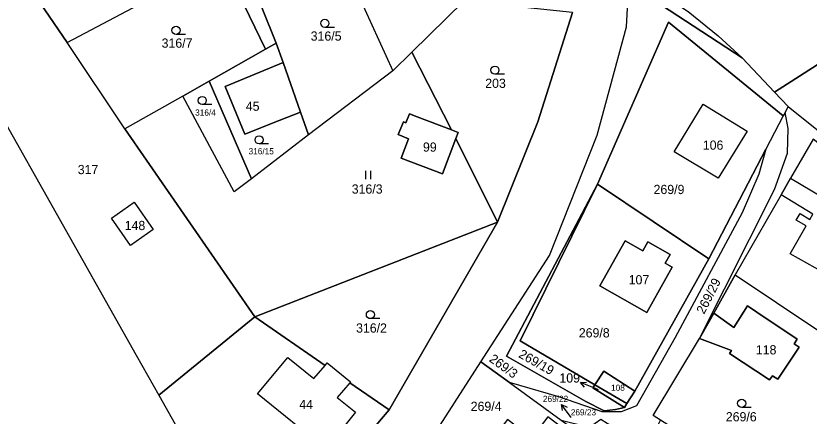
# Model space of a CAD drawing. Extents: x -590606 to -587796, y -1065936 to -1062515.
# Drawn here: x -589191 to -589044.8, y -1064528.5 to -1064454.8 of the extents above; entities that cross this region are included whole.
import ezdxf

# ---------------------------------------------------------------- set-up
doc = ezdxf.new("R2010")
doc.units = 0
for name, color, linetype in [('Parcela nároku', 7, 'Continuous'), ('Parcelní číslo', 7, 'Continuous'), ('Vrstva 30', 7, 'Continuous')]:
    doc.layers.add(name, color=color, linetype=linetype)

msp = doc.modelspace()

# ---------------------------------------------------------------- linework, layer by layer
at = {"layer": 'Parcela nároku'}
for points in [[(-589115.31, -1064437.58), (-589122.6, -1064422.32), (-589132.89, -1064400.67), (-589145.56, -1064374.76), (-589153.23, -1064385.7), (-589150.61, -1064384.42), (-589149.77, -1064386.15), (-589148.31, -1064385.41), (-589145.3, -1064391.43), (-589143.1, -1064390.21), (-589141.76, -1064392.64), (-589144.07, -1064393.88), (-589140.03, -1064401.95), (-589146.68, -1064405.04), (-589154.26, -1064391.41), (-589136.97, -1064430.89), (-589121.53, -1064464.86), (-589118, -1064461.45), (-589108.39, -1064452.07)], [(-589151.26, -1064439.02), (-589150.69, -1064440.44), (-589145.63, -1064453.19), (-589143.01, -1064459.79), (-589144.95, -1064460.89), (-589152.91, -1064444.49), (-589160.29, -1064423.26), (-589159.06, -1064422.32)], [(-589166.49, -1064427.99), (-589190.58, -1064446.38), (-589181.56, -1064459.68), (-589152.91, -1064444.49), (-589160.29, -1064423.26)], [(-589054.48, -1064435.41), (-589077.97, -1064446.72), (-589067.07, -1064453.97), (-589061.52, -1064458.43), (-589057.13, -1064462.5), (-589051.17, -1064468.81), (-589021.42, -1064449.73), (-589042.45, -1064423.68), (-589046.93, -1064428.46)], [(-589151.26, -1064439.02), (-589136.97, -1064430.89), (-589121.53, -1064464.86), (-589137.07, -1064476.7), (-589138.51, -1064472.49), (-589141.75, -1064463.34), (-589143.01, -1064459.79), (-589145.63, -1064453.19), (-589143.02, -1064451.87), (-589135.34, -1064447.9), (-589141.74, -1064435.9), (-589149.27, -1064439.72), (-589150.69, -1064440.44)], [(-589170.89, -1064475.6), (-589181.56, -1064459.68), (-589190.58, -1064446.38), (-589198.19, -1064435.18), (-589208.79, -1064446.47), (-589168.83, -1064517.27), (-589164.65, -1064524.67), (-589146.94, -1064510.23)], [(-589181.56, -1064459.68), (-589152.91, -1064444.49), (-589144.95, -1064460.89), (-589155.37, -1064466.8), (-589160.23, -1064469.56), (-589170.89, -1064475.6)], [(-589232.4, -1064471.45), (-589208.79, -1064446.47), (-589168.83, -1064517.27), (-589164.65, -1064524.67), (-589161.07, -1064530.98), (-589156.51, -1064536.45), (-589159.83, -1064537.55), (-589201.82, -1064551.44)], [(-589078.02, -1064448.81), (-589077.97, -1064446.72), (-589067.07, -1064453.97), (-589061.52, -1064458.43), (-589057.13, -1064462.5)], [(-589057.13, -1064462.5), (-589051.17, -1064468.81), (-589048.65, -1064471.48), (-589049.2, -1064472.55), (-589049.53, -1064473.18), (-589070.66, -1064455.95), (-589083.76, -1064485.8), (-589100.58, -1064517.5), (-589085.95, -1064525.82), (-589082.57, -1064527.52), (-589080.47, -1064527.32), (-589078.82, -1064526.93), (-589078.35, -1064526.19), (-589076.87, -1064523.9), (-589063.23, -1064499.51), (-589052.72, -1064479.3), (-589054.06, -1064483.94), (-589057.13, -1064491.06), (-589069.47, -1064514.03), (-589076.57, -1064526.63), (-589079.42, -1064527.74), (-589082.89, -1064527.75), (-589090.91, -1064524.94), (-589100.01, -1064522.33), (-589105.28, -1064518.51), (-589092.65, -1064498.9), (-589083.82, -1064476.76), (-589078.44, -1064456.79), (-589078.02, -1064448.81)], [(-589021.42, -1064449.73), (-589051.17, -1064468.81), (-589048.65, -1064471.48), (-589029.39, -1064486.89), (-589024.72, -1064490.53), (-589014.96, -1064485.26), (-588999.69, -1064476.66)], [(-589109.44, -1064476.24), (-589109.87, -1064477.37), (-589102.2, -1064492.78), (-589094.76, -1064474.31), (-589088.39, -1064454.14), (-589108.39, -1064452.07), (-589118, -1064461.45), (-589110.67, -1064475.77)], [(-589083.76, -1064485.8), (-589070.66, -1064455.95), (-589049.53, -1064473.18), (-589052.72, -1064479.3), (-589063.23, -1064499.51)], [(-589155.37, -1064466.8), (-589144.95, -1064460.89), (-589143.01, -1064459.79), (-589141.75, -1064463.34), (-589146.05, -1064465.13), (-589152.42, -1064467.78), (-589148.79, -1064476.54), (-589142.48, -1064474.06), (-589138.51, -1064472.49), (-589137.07, -1064476.7), (-589147.59, -1064484.81)], [(-589147.59, -1064484.81), (-589150.73, -1064487.19), (-589160.23, -1064469.56), (-589170.89, -1064475.6), (-589146.94, -1064510.23), (-589102.2, -1064492.78), (-589109.87, -1064477.37), (-589112.36, -1064483.84), (-589119.99, -1064480.97), (-589118.61, -1064477.4), (-589120.53, -1064476.65), (-589119.56, -1064474.27), (-589119.09, -1064474.45), (-589118.45, -1064472.8), (-589117.04, -1064473.35), (-589110.67, -1064475.77), (-589118, -1064461.45), (-589121.53, -1064464.86), (-589137.07, -1064476.7)], [(-589152.42, -1064467.78), (-589146.05, -1064465.13), (-589141.75, -1064463.34), (-589138.51, -1064472.49), (-589142.48, -1064474.06), (-589148.79, -1064476.54)], [(-589155.37, -1064466.8), (-589147.59, -1064484.81), (-589150.73, -1064487.19), (-589160.23, -1064469.56)], [(-589064.29, -1064471.06), (-589056.21, -1064475.99), (-589061.5, -1064484.68), (-589069.67, -1064479.81)], [(-589056.21, -1064475.99), (-589061.5, -1064484.68), (-589069.67, -1064479.81), (-589064.29, -1064471.06)], [(-589118.61, -1064477.4), (-589119.99, -1064480.97), (-589112.36, -1064483.84), (-589109.87, -1064477.37), (-589109.44, -1064476.24), (-589110.67, -1064475.77), (-589117.04, -1064473.35), (-589118.45, -1064472.8), (-589119.09, -1064474.45), (-589119.56, -1064474.27), (-589120.53, -1064476.65)], [(-589076.57, -1064526.63), (-589079.42, -1064527.74), (-589082.89, -1064527.75), (-589090.91, -1064524.94), (-589100.01, -1064522.33), (-589090.45, -1064529.26), (-589085.24, -1064530.57), (-589083.14, -1064529.09), (-589080.83, -1064530.54), (-589063.47, -1064541.46), (-589072.75, -1064530.48), (-589072.17, -1064529.26), (-589073.49, -1064528.42), (-589065, -1064514.23), (-589051.15, -1064486.78), (-589048.73, -1064480.06), (-589048.6, -1064475.49), (-589049.2, -1064472.55), (-589049.53, -1064473.18), (-589052.72, -1064479.3), (-589054.06, -1064483.94), (-589057.13, -1064491.06), (-589069.47, -1064514.03)], [(-589040.6, -1064502.91), (-589048.23, -1064498.62), (-589045.3, -1064493.48), (-589047.13, -1064492.43), (-589046.44, -1064491.21), (-589044.61, -1064492.26), (-589044.06, -1064491.3), (-589049.94, -1064487.74), (-589058.39, -1064502.47), (-589035.51, -1064517.76), (-589021.25, -1064495.37), (-589044.04, -1064477.46), (-589048.18, -1064484.68), (-589042.27, -1064488.16), (-589042.15, -1064487.94), (-589034.46, -1064492.34)], [(-589046.44, -1064491.21), (-589044.61, -1064492.26), (-589044.06, -1064491.3), (-589049.94, -1064487.74), (-589048.18, -1064484.68), (-589042.27, -1064488.16), (-589042.15, -1064487.94), (-589034.46, -1064492.34), (-589040.6, -1064502.91), (-589048.23, -1064498.62), (-589045.3, -1064493.48), (-589047.13, -1064492.43)], [(-589100.58, -1064517.5), (-589083.76, -1064485.8), (-589098.01, -1064514.65), (-589084.24, -1064522.73), (-589084.62, -1064523.3), (-589078.82, -1064526.93), (-589080.47, -1064527.32), (-589082.57, -1064527.52), (-589085.95, -1064525.82)], [(-589083.76, -1064485.8), (-589063.23, -1064499.51), (-589076.87, -1064523.9), (-589082.61, -1064520.26), (-589084.24, -1064522.73), (-589098.01, -1064514.65)], [(-589169.84, -1064497.07), (-589173.37, -1064492.04), (-589169.2, -1064489.1), (-589165.66, -1064494.13)], [(-589173.37, -1064492.04), (-589169.2, -1064489.1), (-589165.66, -1064494.13), (-589169.84, -1064497.07)], [(-589129.31, -1064522.2), (-589129.44, -1064522.36), (-589122.18, -1064527.39), (-589102.2, -1064492.78), (-589146.94, -1064510.23), (-589134, -1064519.2), (-589133.61, -1064518.69)], [(-589074.47, -1064496.4), (-589075.41, -1064498.05), (-589078.65, -1064496.2), (-589083.36, -1064504.53), (-589074.68, -1064509.44), (-589070.01, -1064501.07), (-589071.3, -1064500.34), (-589070.38, -1064498.73)], [(-589074.68, -1064509.44), (-589083.36, -1064504.53), (-589078.65, -1064496.2), (-589075.41, -1064498.05), (-589074.47, -1064496.4), (-589070.38, -1064498.73), (-589071.3, -1064500.34), (-589070.01, -1064501.07)], [(-589073.49, -1064528.42), (-589065, -1064514.23), (-589059.07, -1064516.43), (-589059.42, -1064516.96), (-589052.04, -1064521.86), (-589051.51, -1064521.07), (-589050.55, -1064521.72), (-589046.57, -1064515.81), (-589047.52, -1064515.17), (-589046.98, -1064514.36), (-589054.41, -1064509.35), (-589056.13, -1064508.19), (-589058.63, -1064512.18), (-589062.32, -1064509.54), (-589058.39, -1064502.47), (-589035.51, -1064517.76), (-589051.04, -1064542.74), (-589072.17, -1064529.26)], [(-589065, -1064514.23), (-589062.97, -1064510.67), (-589062.32, -1064509.54), (-589058.63, -1064512.18), (-589056.13, -1064508.19), (-589054.41, -1064509.35), (-589046.98, -1064514.36), (-589047.52, -1064515.17), (-589046.57, -1064515.81), (-589050.55, -1064521.72), (-589051.51, -1064521.07), (-589052.04, -1064521.86), (-589059.42, -1064516.96), (-589059.07, -1064516.43)], [(-589129.44, -1064522.36), (-589131.76, -1064525.09), (-589128.4, -1064527.82), (-589133.87, -1064534.63), (-589146.45, -1064524.44), (-589140.87, -1064517.69), (-589136.06, -1064521.6), (-589134, -1064519.2), (-589146.94, -1064510.23), (-589164.65, -1064524.67), (-589161.07, -1064530.98), (-589156.51, -1064536.45), (-589143.75, -1064552.4), (-589134.1, -1064541.79), (-589130.39, -1064537.32), (-589123.98, -1064529.48), (-589122.18, -1064527.39)], [(-589131.76, -1064525.09), (-589128.4, -1064527.82), (-589133.87, -1064534.63), (-589146.45, -1064524.44), (-589140.87, -1064517.69), (-589136.06, -1064521.6), (-589134, -1064519.2), (-589133.61, -1064518.69), (-589129.31, -1064522.2), (-589129.44, -1064522.36)], [(-589105.28, -1064518.51), (-589100.01, -1064522.33), (-589090.45, -1064529.26), (-589086.97, -1064531.78), (-589093.87, -1064538.29), (-589088.84, -1064531.79), (-589092.91, -1064528.64), (-589095.97, -1064532.57), (-589100.35, -1064529.15), (-589108.67, -1064540.01), (-589115.01, -1064533.6)], [(-589084.24, -1064522.73), (-589082.61, -1064520.26), (-589076.87, -1064523.9), (-589078.35, -1064526.19)], [(-589084.62, -1064523.3), (-589084.24, -1064522.73), (-589078.35, -1064526.19), (-589078.82, -1064526.93)]]:
    msp.add_lwpolyline(points, close=True, dxfattribs=at)
for points in [[(-589219.53, -1064748.72), (-589186.36, -1064642.57), (-589183.62, -1064634.01), (-589183.45, -1064633.66), (-589181.35, -1064629.23), (-589179.39, -1064625.08), (-589169.88, -1064604.99), (-589163.72, -1064594.94), (-589149.8, -1064577.36), (-589123.77, -1064546.13), (-589122.47, -1064544.56), (-589115.01, -1064533.6), (-589105.28, -1064518.51), (-589092.65, -1064498.9), (-589083.82, -1064476.76), (-589078.44, -1064456.79), (-589078.02, -1064448.81)], [(-589088.39, -1064454.14), (-589094.76, -1064474.31), (-589102.2, -1064492.78), (-589122.18, -1064527.39), (-589123.98, -1064529.48), (-589130.39, -1064537.32), (-589134.1, -1064541.79), (-589143.75, -1064552.4), (-589146.65, -1064555.73), (-589149.4, -1064559.72), (-589167.86, -1064579.14), (-589174.88, -1064589.8), (-589180.97, -1064599.01), (-589185.08, -1064607.88), (-589192.01, -1064622.83)], [(-589044.04, -1064477.46), (-589048.18, -1064484.68), (-589049.94, -1064487.74), (-589058.39, -1064502.47), (-589062.32, -1064509.54), (-589062.97, -1064510.67), (-589065, -1064514.23), (-589051.15, -1064486.78), (-589048.73, -1064480.06), (-589048.6, -1064475.49), (-589049.2, -1064472.55), (-589048.65, -1064471.48), (-589029.39, -1064486.89)]]:
    msp.add_lwpolyline(points, dxfattribs=at)
at = {"layer": 'Parcelní číslo'}
for p, q in [((-589084.13, -1064523.44), (-589086.92, -1064522.34)), ((-589083.56, -1064523.67), (-589084.13, -1064523.44)), ((-589088.61, -1064528.8), (-589090.39, -1064526.38))]:
    msp.add_line(p, q, dxfattribs=at)
for points in [[(-589086.17, -1064523.17), (-589086.92, -1064522.34), (-589085.81, -1064522.24)], [(-589090.2, -1064527.48), (-589090.39, -1064526.38), (-589089.39, -1064526.89)]]:
    msp.add_lwpolyline(points, dxfattribs=at)
at = {"layer": 'Vrstva 30'}
for p, q in [((-589132.28, -1064456.88), (-589134.03, -1064456.88)), ((-589159.72, -1064458.18), (-589161.47, -1064458.18)), ((-589100.94, -1064465.52), (-589102.69, -1064465.52)), ((-589154.89, -1064471.1), (-589156.64, -1064471.1)), ((-589144.41, -1064478.36), (-589146.16, -1064478.36)), ((-589126.56, -1064483.34), (-589126.56, -1064484.84)), ((-589125.54, -1064484.84), (-589125.54, -1064483.34)), ((-589123.89, -1064510.56), (-589125.64, -1064510.56)), ((-589055.44, -1064526.92), (-589057.19, -1064526.92))]:
    msp.add_line(p, q, dxfattribs=at)
for centre in [(-589134.03, -1064456.13), (-589161.47, -1064457.43), (-589102.69, -1064464.77), (-589156.64, -1064470.35), (-589146.16, -1064477.61), (-589125.64, -1064509.81), (-589057.19, -1064526.17)]:
    msp.add_circle(centre, 0.75, dxfattribs=at)

# ---------------------------------------------------------------- texts
at = {"layer": 'Parcela nároku'}
for s, height, p in [('316/5', 1.7, (-589136.65, -1064459.33)), ('316/7', 1.7, (-589164.13, -1064460.63)), ('203', 1.7, (-589104.47, -1064468.03)), ('45', 1.7, (-589148.61, -1064472.25)), ('316/4', 1.14, (-589157.95, -1064473.15)), ('99', 1.7, (-589115.95, -1064479.79)), ('106', 1.7, (-589064.36, -1064479.43)), ('316/15', 1.14, (-589148.1, -1064480.28)), ('317', 1.7, (-589179.59, -1064483.93)), ('316/3', 1.7, (-589129.08, -1064487.52)), ('269/9', 1.7, (-589073.44, -1064487.6)), ('148', 1.7, (-589170.94, -1064494.24)), ('107', 1.7, (-589078.03, -1064504.24)), ('316/2', 1.7, (-589128.28, -1064513.13)), ('269/8', 1.7, (-589087.22, -1064514.02)), ('118', 1.7, (-589054.58, -1064517.15)), ('108', 1.14, (-589081.28, -1064523.86)), ('109', 0.1, (-589083.64, -1064523.67)), ('44', 1.7, (-589138.76, -1064527.22)), ('269/4', 1.7, (-589107.15, -1064527.56)), ('269/6', 1.7, (-589060.12, -1064529.49))]:
    msp.add_text(s, height=height, dxfattribs=at).set_placement(p)
for s, rotation, p in [('269/29', 63, (-589064.13, -1064509.86)), ('269/3', 324, (-589103.88, -1064518.32)), ('269/19', 330.4696, (-589098.46, -1064517.59))]:
    msp.add_text(s, height=1.7, rotation=rotation, dxfattribs=at).set_placement(p)
at = {"layer": 'Parcelní číslo'}
for s, height, p in [('109', 1.7, (-589090.8, -1064522.34)), ('269/22', 1.14, (-589093.84, -1064525.91)), ('269/23', 1.14, (-589088.7, -1064528.39))]:
    msp.add_text(s, height=height, dxfattribs=at).set_placement(p)

doc.saveas('drawing.dxf')
